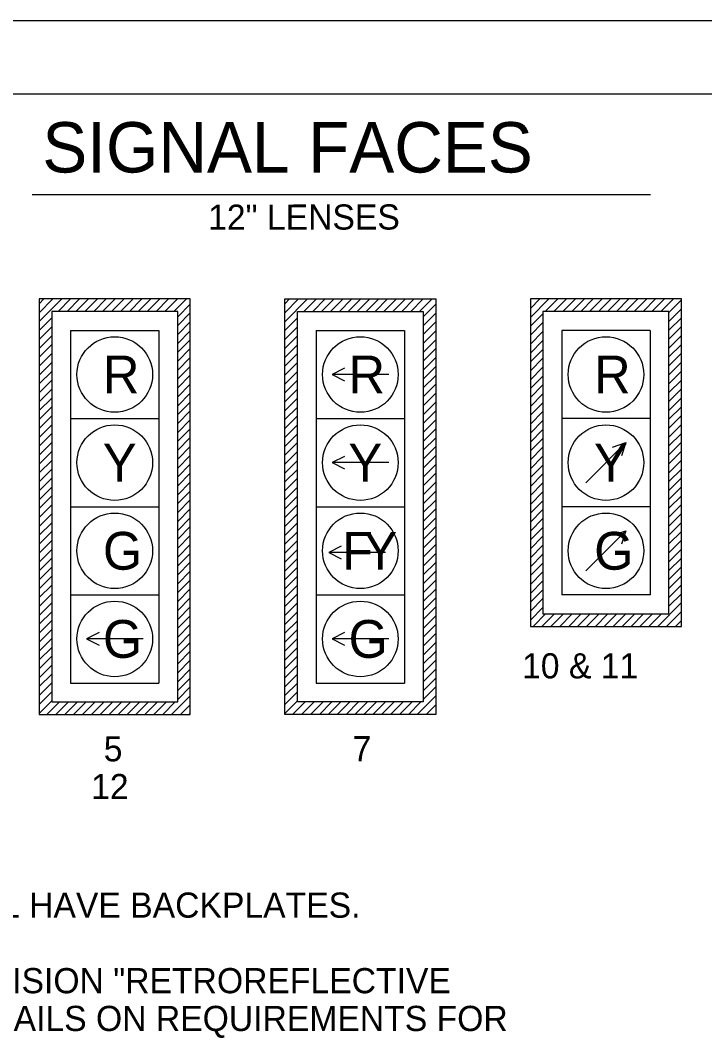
# Model space of a CAD drawing. Extents: x 1710114 to 1711114, y 557211 to 557851.
# Drawn here: x 1710384.3 to 1710492.9, y 557689.1 to 557851.1 of the extents above; entities that cross this region are included whole.
import ezdxf

# ---------------------------------------------------------------- set-up
doc = ezdxf.new("R2010")
doc.units = 0
for name, color, linetype in [('E_Existing ROW', 7, 'Continuous'), ('R_Alt Surface', 7, 'Continuous'), ('R_Alt Surface Annot', 7, 'Continuous'), ('R_Dimension', 7, 'Continuous')]:
    doc.layers.add(name, color=color, linetype=linetype)

msp = doc.modelspace()

# ---------------------------------------------------------------- linework, layer by layer
at = {"layer": 'E_Existing ROW'}
for p, q in [((1710411.23, 557806.9), (1710387.23, 557806.9)), ((1710387.23, 557806.9), (1710387.23, 557740.9)), ((1710387.23, 557803.3), (1710390.82, 557806.9)), ((1710387.23, 557804.72), (1710389.4, 557806.9)), ((1710387.23, 557806.13), (1710387.99, 557806.9)), ((1710390.23, 557804.9), (1710392.23, 557806.9)), ((1710391.65, 557804.9), (1710393.65, 557806.9)), ((1710393.06, 557804.9), (1710395.06, 557806.9)), ((1710394.48, 557804.9), (1710396.48, 557806.9)), ((1710395.89, 557804.9), (1710397.89, 557806.9)), ((1710397.3, 557804.9), (1710399.3, 557806.9)), ((1710398.72, 557804.9), (1710400.72, 557806.9)), ((1710400.13, 557804.9), (1710402.13, 557806.9)), ((1710401.55, 557804.9), (1710403.55, 557806.9)), ((1710402.96, 557804.9), (1710404.96, 557806.9)), ((1710404.38, 557804.9), (1710406.38, 557806.9)), ((1710405.79, 557804.9), (1710407.79, 557806.9)), ((1710407.2, 557804.9), (1710409.2, 557806.9)), ((1710408.62, 557804.9), (1710410.62, 557806.9)), ((1710411.23, 557740.9), (1710411.23, 557806.9)), ((1710426.23, 557740.9), (1710426.23, 557806.9)), ((1710426.23, 557806.9), (1710450.23, 557806.9)), ((1710426.23, 557803.29), (1710429.83, 557806.9)), ((1710426.23, 557804.7), (1710428.42, 557806.9)), ((1710426.23, 557806.12), (1710427, 557806.9)), ((1710429.25, 557804.9), (1710431.25, 557806.9)), ((1710430.66, 557804.9), (1710432.66, 557806.9)), ((1710432.08, 557804.9), (1710434.08, 557806.9)), ((1710433.49, 557804.9), (1710435.49, 557806.9)), ((1710434.9, 557804.9), (1710436.9, 557806.9)), ((1710436.32, 557804.9), (1710438.32, 557806.9)), ((1710437.73, 557804.9), (1710439.73, 557806.9)), ((1710439.15, 557804.9), (1710441.15, 557806.9)), ((1710440.56, 557804.9), (1710442.56, 557806.9)), ((1710441.98, 557804.9), (1710443.98, 557806.9)), ((1710443.39, 557804.9), (1710445.39, 557806.9)), ((1710444.8, 557804.9), (1710446.8, 557806.9)), ((1710446.22, 557804.9), (1710448.22, 557806.9)), ((1710447.63, 557804.9), (1710449.63, 557806.9)), ((1710450.23, 557806.9), (1710450.23, 557740.9)), ((1710489.23, 557806.9), (1710465.23, 557806.9)), ((1710465.23, 557806.9), (1710465.23, 557754.9)), ((1710465.23, 557803.97), (1710468.15, 557806.9)), ((1710465.23, 557805.39), (1710466.74, 557806.9)), ((1710465.23, 557806.8), (1710465.32, 557806.9)), ((1710467.57, 557804.9), (1710469.57, 557806.9)), ((1710468.98, 557804.9), (1710470.98, 557806.9)), ((1710470.39, 557804.9), (1710472.39, 557806.9)), ((1710471.81, 557804.9), (1710473.81, 557806.9)), ((1710473.22, 557804.9), (1710475.22, 557806.9)), ((1710474.64, 557804.9), (1710476.64, 557806.9)), ((1710476.05, 557804.9), (1710478.05, 557806.9)), ((1710477.47, 557804.9), (1710479.47, 557806.9)), ((1710478.88, 557804.9), (1710480.88, 557806.9)), ((1710480.29, 557804.9), (1710482.29, 557806.9)), ((1710481.71, 557804.9), (1710483.71, 557806.9)), ((1710483.12, 557804.9), (1710485.12, 557806.9)), ((1710484.54, 557804.9), (1710486.54, 557806.9)), ((1710485.95, 557804.9), (1710487.95, 557806.9)), ((1710487.23, 557804.76), (1710489.23, 557806.76)), ((1710489.23, 557754.9), (1710489.23, 557806.9)), ((1710409.23, 557804.09), (1710411.23, 557806.09)), ((1710448.23, 557804.08), (1710450.23, 557806.08)), ((1710487.23, 557803.34), (1710489.23, 557805.34)), ((1710387.23, 557801.89), (1710389.23, 557803.89)), ((1710409.23, 557802.68), (1710411.23, 557804.68)), ((1710409.23, 557801.26), (1710411.23, 557803.26)), ((1710426.23, 557801.88), (1710428.23, 557803.88)), ((1710448.23, 557802.66), (1710450.23, 557804.66)), ((1710448.23, 557801.25), (1710450.23, 557803.25)), ((1710465.23, 557802.56), (1710467.23, 557804.56)), ((1710465.23, 557801.14), (1710467.23, 557803.14)), ((1710487.23, 557801.93), (1710489.23, 557803.93)), ((1710387.23, 557800.48), (1710389.23, 557802.48)), ((1710392.23, 557801.9), (1710406.23, 557801.9)), ((1710392.23, 557801.9), (1710392.23, 557787.9)), ((1710406.23, 557801.9), (1710406.23, 557787.9)), ((1710409.23, 557799.85), (1710411.23, 557801.85)), ((1710426.23, 557800.46), (1710428.23, 557802.46)), ((1710431.23, 557801.9), (1710445.23, 557801.9)), ((1710431.23, 557801.9), (1710431.23, 557787.9)), ((1710445.23, 557801.9), (1710445.23, 557787.9)), ((1710448.23, 557799.83), (1710450.23, 557801.83)), ((1710465.23, 557799.73), (1710467.23, 557801.73)), ((1710484.23, 557801.9), (1710470.23, 557801.9)), ((1710470.23, 557801.9), (1710470.23, 557787.9)), ((1710484.23, 557801.9), (1710484.23, 557787.9)), ((1710487.23, 557800.52), (1710489.23, 557802.52)), ((1710387.23, 557799.06), (1710389.23, 557801.06)), ((1710409.23, 557798.43), (1710411.23, 557800.43)), ((1710426.23, 557799.05), (1710428.23, 557801.05)), ((1710448.23, 557798.42), (1710450.23, 557800.42)), ((1710465.23, 557798.31), (1710467.23, 557800.31)), ((1710487.23, 557799.1), (1710489.23, 557801.1)), ((1710387.23, 557797.65), (1710389.23, 557799.65)), ((1710409.23, 557797.02), (1710411.23, 557799.02)), ((1710426.23, 557797.63), (1710428.23, 557799.63)), ((1710448.23, 557797.01), (1710450.23, 557799.01)), ((1710465.23, 557796.9), (1710467.23, 557798.9)), ((1710487.23, 557797.69), (1710489.23, 557799.69)), ((1710487.23, 557796.27), (1710489.23, 557798.27)), ((1710387.23, 557796.23), (1710389.23, 557798.23)), ((1710387.23, 557794.82), (1710389.23, 557796.82)), ((1710409.23, 557795.61), (1710411.23, 557797.61)), ((1710426.23, 557796.22), (1710428.23, 557798.22)), ((1710426.23, 557794.8), (1710428.23, 557796.8)), ((1710448.23, 557795.59), (1710450.23, 557797.59)), ((1710465.23, 557795.49), (1710467.23, 557797.49)), ((1710487.23, 557794.86), (1710489.23, 557796.86)), ((1710387.23, 557793.4), (1710389.23, 557795.4)), ((1710409.23, 557794.19), (1710411.23, 557796.19)), ((1710426.23, 557793.39), (1710428.23, 557795.39)), ((1710448.23, 557794.18), (1710450.23, 557796.18)), ((1710465.23, 557794.07), (1710467.23, 557796.07)), ((1710487.23, 557793.44), (1710489.23, 557795.44)), ((1710387.23, 557791.99), (1710389.23, 557793.99)), ((1710409.23, 557792.78), (1710411.23, 557794.78)), ((1710426.23, 557791.98), (1710428.23, 557793.98)), ((1710442.73, 557794.9), (1710433.73, 557794.9)), ((1710448.23, 557792.76), (1710450.23, 557794.76)), ((1710465.23, 557792.66), (1710467.23, 557794.66)), ((1710487.23, 557792.03), (1710489.23, 557794.03)), ((1710387.23, 557790.58), (1710389.23, 557792.58)), ((1710409.23, 557791.36), (1710411.23, 557793.36)), ((1710409.23, 557789.95), (1710411.23, 557791.95)), ((1710426.23, 557790.56), (1710428.23, 557792.56)), ((1710448.23, 557791.35), (1710450.23, 557793.35)), ((1710448.23, 557789.93), (1710450.23, 557791.93)), ((1710465.23, 557791.24), (1710467.23, 557793.24)), ((1710465.23, 557789.83), (1710467.23, 557791.83)), ((1710487.23, 557790.62), (1710489.23, 557792.62)), ((1710387.23, 557789.16), (1710389.23, 557791.16)), ((1710409.23, 557788.53), (1710411.23, 557790.53)), ((1710426.23, 557789.15), (1710428.23, 557791.15)), ((1710448.23, 557788.52), (1710450.23, 557790.52)), ((1710465.23, 557788.42), (1710467.23, 557790.42)), ((1710487.23, 557789.2), (1710489.23, 557791.2)), ((1710387.23, 557787.75), (1710389.23, 557789.75)), ((1710409.23, 557787.12), (1710411.23, 557789.12)), ((1710426.23, 557787.73), (1710428.23, 557789.73)), ((1710448.23, 557787.11), (1710450.23, 557789.11)), ((1710465.23, 557787), (1710467.23, 557789)), ((1710487.23, 557787.79), (1710489.23, 557789.79)), ((1710387.23, 557786.33), (1710389.23, 557788.33)), ((1710387.23, 557784.92), (1710389.23, 557786.92)), ((1710392.23, 557787.9), (1710406.23, 557787.9)), ((1710392.23, 557787.9), (1710392.23, 557773.9)), ((1710406.23, 557787.9), (1710406.23, 557773.9)), ((1710409.23, 557785.71), (1710411.23, 557787.71)), ((1710426.23, 557786.32), (1710428.23, 557788.32)), ((1710431.23, 557787.9), (1710445.23, 557787.9)), ((1710431.23, 557787.9), (1710431.23, 557773.9)), ((1710445.23, 557787.9), (1710445.23, 557773.9)), ((1710448.23, 557785.69), (1710450.23, 557787.69)), ((1710465.23, 557785.59), (1710467.23, 557787.59)), ((1710484.23, 557787.9), (1710470.23, 557787.9)), ((1710470.23, 557787.9), (1710470.23, 557773.9)), ((1710484.23, 557787.9), (1710484.23, 557773.9)), ((1710487.23, 557786.37), (1710489.23, 557788.37)), ((1710487.23, 557784.96), (1710489.23, 557786.96)), ((1710387.23, 557783.51), (1710389.23, 557785.51)), ((1710409.23, 557784.29), (1710411.23, 557786.29)), ((1710426.23, 557784.91), (1710428.23, 557786.91)), ((1710426.23, 557783.49), (1710428.23, 557785.49)), ((1710448.23, 557784.28), (1710450.23, 557786.28)), ((1710465.23, 557784.17), (1710467.23, 557786.17)), ((1710487.23, 557783.55), (1710489.23, 557785.55)), ((1710387.23, 557782.09), (1710389.23, 557784.09)), ((1710409.23, 557782.88), (1710411.23, 557784.88)), ((1710426.23, 557782.08), (1710428.23, 557784.08)), ((1710448.23, 557782.86), (1710450.23, 557784.86)), ((1710465.23, 557782.76), (1710467.23, 557784.76)), ((1710474.04, 557777.72), (1710480.41, 557784.08)), ((1710487.23, 557782.13), (1710489.23, 557784.13)), ((1710387.23, 557780.68), (1710389.23, 557782.68)), ((1710409.23, 557781.46), (1710411.23, 557783.46)), ((1710426.23, 557780.66), (1710428.23, 557782.66)), ((1710448.23, 557781.45), (1710450.23, 557783.45)), ((1710465.23, 557781.34), (1710467.23, 557783.34)), ((1710487.23, 557780.72), (1710489.23, 557782.72)), ((1710387.23, 557779.26), (1710389.23, 557781.26)), ((1710409.23, 557780.05), (1710411.23, 557782.05)), ((1710409.23, 557778.64), (1710411.23, 557780.64)), ((1710426.23, 557779.25), (1710428.23, 557781.25)), ((1710442.73, 557780.9), (1710433.73, 557780.9)), ((1710448.23, 557780.04), (1710450.23, 557782.04)), ((1710448.23, 557778.62), (1710450.23, 557780.62)), ((1710465.23, 557779.93), (1710467.23, 557781.93)), ((1710465.23, 557778.52), (1710467.23, 557780.52)), ((1710487.23, 557779.3), (1710489.23, 557781.3)), ((1710387.23, 557777.85), (1710389.23, 557779.85)), ((1710409.23, 557777.22), (1710411.23, 557779.22)), ((1710426.23, 557777.83), (1710428.23, 557779.83)), ((1710448.23, 557777.21), (1710450.23, 557779.21)), ((1710465.23, 557777.1), (1710467.23, 557779.1)), ((1710487.23, 557777.89), (1710489.23, 557779.89)), ((1710387.23, 557776.43), (1710389.23, 557778.43)), ((1710409.23, 557775.81), (1710411.23, 557777.81)), ((1710426.23, 557776.42), (1710428.23, 557778.42)), ((1710448.23, 557775.79), (1710450.23, 557777.79)), ((1710465.23, 557775.69), (1710467.23, 557777.69)), ((1710487.23, 557776.47), (1710489.23, 557778.47)), ((1710387.23, 557775.02), (1710389.23, 557777.02)), ((1710387.23, 557773.61), (1710389.23, 557775.61)), ((1710409.23, 557774.39), (1710411.23, 557776.39)), ((1710426.23, 557775.01), (1710428.23, 557777.01)), ((1710426.23, 557773.59), (1710428.23, 557775.59)), ((1710448.23, 557774.38), (1710450.23, 557776.38)), ((1710465.23, 557774.27), (1710467.23, 557776.27)), ((1710487.23, 557775.06), (1710489.23, 557777.06)), ((1710487.23, 557773.65), (1710489.23, 557775.65)), ((1710387.23, 557772.19), (1710389.23, 557774.19)), ((1710409.23, 557772.98), (1710411.23, 557774.98)), ((1710426.23, 557772.18), (1710428.23, 557774.18)), ((1710448.23, 557772.96), (1710450.23, 557774.96)), ((1710465.23, 557772.86), (1710467.23, 557774.86)), ((1710487.23, 557772.23), (1710489.23, 557774.23)), ((1710387.23, 557770.78), (1710389.23, 557772.78)), ((1710392.23, 557773.9), (1710406.23, 557773.9)), ((1710392.23, 557773.9), (1710392.23, 557759.9)), ((1710406.23, 557773.9), (1710406.23, 557759.9)), ((1710409.23, 557771.56), (1710411.23, 557773.56)), ((1710426.23, 557770.76), (1710428.23, 557772.76)), ((1710431.23, 557773.9), (1710445.23, 557773.9)), ((1710431.23, 557773.9), (1710431.23, 557759.9)), ((1710445.23, 557773.9), (1710445.23, 557759.9)), ((1710448.23, 557771.55), (1710450.23, 557773.55)), ((1710465.23, 557771.44), (1710467.23, 557773.44)), ((1710484.23, 557773.9), (1710470.23, 557773.9)), ((1710470.23, 557773.9), (1710470.23, 557759.9)), ((1710484.23, 557773.9), (1710484.23, 557759.9)), ((1710487.23, 557770.82), (1710489.23, 557772.82)), ((1710387.23, 557769.36), (1710389.23, 557771.36)), ((1710409.23, 557770.15), (1710411.23, 557772.15)), ((1710409.23, 557768.74), (1710411.23, 557770.74)), ((1710426.23, 557769.35), (1710428.23, 557771.35)), ((1710448.23, 557770.14), (1710450.23, 557772.14)), ((1710448.23, 557768.72), (1710450.23, 557770.72)), ((1710465.23, 557770.03), (1710467.23, 557772.03)), ((1710487.23, 557769.4), (1710489.23, 557771.4)), ((1710387.23, 557767.95), (1710389.23, 557769.95)), ((1710409.23, 557767.32), (1710411.23, 557769.32)), ((1710426.23, 557767.93), (1710428.23, 557769.93)), ((1710448.23, 557767.31), (1710450.23, 557769.31)), ((1710465.23, 557768.62), (1710467.23, 557770.62)), ((1710465.23, 557767.2), (1710467.23, 557769.2)), ((1710474.04, 557763.72), (1710480.41, 557770.08)), ((1710487.23, 557767.99), (1710489.23, 557769.99)), ((1710387.23, 557766.53), (1710389.23, 557768.53)), ((1710409.23, 557765.91), (1710411.23, 557767.91)), ((1710426.23, 557766.52), (1710428.23, 557768.52)), ((1710448.23, 557765.89), (1710450.23, 557767.89)), ((1710465.23, 557765.79), (1710467.23, 557767.79)), ((1710487.23, 557766.57), (1710489.23, 557768.57)), ((1710387.23, 557765.12), (1710389.23, 557767.12)), ((1710409.23, 557764.49), (1710411.23, 557766.49)), ((1710426.23, 557765.11), (1710428.23, 557767.11)), ((1710442.2, 557766.62), (1710433.2, 557766.62)), ((1710448.23, 557764.48), (1710450.23, 557766.48)), ((1710465.23, 557764.37), (1710467.23, 557766.37)), ((1710487.23, 557765.16), (1710489.23, 557767.16)), ((1710387.23, 557763.71), (1710389.23, 557765.71)), ((1710387.23, 557762.29), (1710389.23, 557764.29)), ((1710409.23, 557763.08), (1710411.23, 557765.08)), ((1710426.23, 557763.69), (1710428.23, 557765.69)), ((1710426.23, 557762.28), (1710428.23, 557764.28)), ((1710448.23, 557763.06), (1710450.23, 557765.06)), ((1710465.23, 557762.96), (1710467.23, 557764.96)), ((1710487.23, 557763.75), (1710489.23, 557765.75)), ((1710487.23, 557762.33), (1710489.23, 557764.33)), ((1710387.23, 557760.88), (1710389.23, 557762.88)), ((1710409.23, 557761.66), (1710411.23, 557763.66)), ((1710426.23, 557760.86), (1710428.23, 557762.86)), ((1710448.23, 557761.65), (1710450.23, 557763.65)), ((1710465.23, 557761.55), (1710467.23, 557763.55)), ((1710487.23, 557760.92), (1710489.23, 557762.92)), ((1710387.23, 557759.46), (1710389.23, 557761.46)), ((1710409.23, 557760.25), (1710411.23, 557762.25)), ((1710426.23, 557759.45), (1710428.23, 557761.45)), ((1710448.23, 557760.24), (1710450.23, 557762.24)), ((1710465.23, 557760.13), (1710467.23, 557762.13)), ((1710487.23, 557759.5), (1710489.23, 557761.5)), ((1710387.23, 557758.05), (1710389.23, 557760.05)), ((1710392.23, 557759.9), (1710406.23, 557759.9)), ((1710392.23, 557759.9), (1710392.23, 557745.9)), ((1710406.23, 557759.9), (1710406.23, 557745.9)), ((1710409.23, 557758.84), (1710411.23, 557760.84)), ((1710409.23, 557757.42), (1710411.23, 557759.42)), ((1710426.23, 557758.04), (1710428.23, 557760.04)), ((1710431.23, 557759.9), (1710445.23, 557759.9)), ((1710431.23, 557759.9), (1710431.23, 557745.9)), ((1710445.23, 557759.9), (1710445.23, 557745.9)), ((1710448.23, 557758.82), (1710450.23, 557760.82)), ((1710448.23, 557757.41), (1710450.23, 557759.41)), ((1710465.23, 557758.72), (1710467.23, 557760.72)), ((1710484.23, 557759.9), (1710470.23, 557759.9)), ((1710487.23, 557758.09), (1710489.23, 557760.09)), ((1710387.23, 557756.64), (1710389.23, 557758.64)), ((1710409.23, 557756.01), (1710411.23, 557758.01)), ((1710426.23, 557756.62), (1710428.23, 557758.62)), ((1710448.23, 557755.99), (1710450.23, 557757.99)), ((1710465.23, 557757.3), (1710467.23, 557759.3)), ((1710465.23, 557755.89), (1710467.23, 557757.89)), ((1710485.45, 557754.9), (1710489.23, 557758.68)), ((1710387.23, 557755.22), (1710389.23, 557757.22)), ((1710409.23, 557754.59), (1710411.23, 557756.59)), ((1710426.23, 557755.21), (1710428.23, 557757.21)), ((1710448.23, 557754.58), (1710450.23, 557756.58)), ((1710465.65, 557754.9), (1710467.65, 557756.9)), ((1710467.06, 557754.9), (1710469.06, 557756.9)), ((1710468.48, 557754.9), (1710470.48, 557756.9)), ((1710469.89, 557754.9), (1710471.89, 557756.9)), ((1710471.31, 557754.9), (1710473.31, 557756.9)), ((1710472.72, 557754.9), (1710474.72, 557756.9)), ((1710474.13, 557754.9), (1710476.13, 557756.9)), ((1710475.55, 557754.9), (1710477.55, 557756.9)), ((1710476.96, 557754.9), (1710478.96, 557756.9)), ((1710478.38, 557754.9), (1710480.38, 557756.9)), ((1710479.79, 557754.9), (1710481.79, 557756.9)), ((1710481.21, 557754.9), (1710483.21, 557756.9)), ((1710482.62, 557754.9), (1710484.62, 557756.9)), ((1710484.03, 557754.9), (1710486.03, 557756.9)), ((1710486.86, 557754.9), (1710489.23, 557757.26)), ((1710387.23, 557753.81), (1710389.23, 557755.81)), ((1710409.23, 557753.18), (1710411.23, 557755.18)), ((1710426.23, 557753.79), (1710428.23, 557755.79)), ((1710448.23, 557753.17), (1710450.23, 557755.17)), ((1710465.23, 557754.9), (1710489.23, 557754.9)), ((1710488.28, 557754.9), (1710489.23, 557755.85)), ((1710387.23, 557752.39), (1710389.23, 557754.39)), ((1710387.23, 557750.98), (1710389.23, 557752.98)), ((1710403.73, 557752.9), (1710394.73, 557752.9)), ((1710409.23, 557751.77), (1710411.23, 557753.77)), ((1710426.23, 557752.38), (1710428.23, 557754.38)), ((1710426.23, 557750.96), (1710428.23, 557752.96)), ((1710442.73, 557752.9), (1710433.73, 557752.9)), ((1710448.23, 557751.75), (1710450.23, 557753.75)), ((1710387.23, 557749.56), (1710389.23, 557751.56)), ((1710409.23, 557750.35), (1710411.23, 557752.35)), ((1710426.23, 557749.55), (1710428.23, 557751.55)), ((1710448.23, 557750.34), (1710450.23, 557752.34)), ((1710387.23, 557748.15), (1710389.23, 557750.15)), ((1710409.23, 557748.94), (1710411.23, 557750.94)), ((1710426.23, 557748.14), (1710428.23, 557750.14)), ((1710448.23, 557748.92), (1710450.23, 557750.92)), ((1710387.23, 557746.74), (1710389.23, 557748.74)), ((1710409.23, 557747.52), (1710411.23, 557749.52)), ((1710409.23, 557746.11), (1710411.23, 557748.11)), ((1710426.23, 557746.72), (1710428.23, 557748.72)), ((1710448.23, 557747.51), (1710450.23, 557749.51)), ((1710448.23, 557746.09), (1710450.23, 557748.09)), ((1710387.23, 557745.32), (1710389.23, 557747.32)), ((1710409.23, 557744.69), (1710411.23, 557746.69)), ((1710426.23, 557745.31), (1710428.23, 557747.31)), ((1710448.23, 557744.68), (1710450.23, 557746.68)), ((1710387.23, 557743.91), (1710389.23, 557745.91)), ((1710392.23, 557745.9), (1710406.23, 557745.9)), ((1710409.23, 557743.28), (1710411.23, 557745.28)), ((1710426.23, 557743.89), (1710428.23, 557745.89)), ((1710431.23, 557745.9), (1710445.23, 557745.9)), ((1710448.23, 557743.27), (1710450.23, 557745.27)), ((1710387.23, 557742.49), (1710389.23, 557744.49)), ((1710408.26, 557740.9), (1710411.23, 557743.87)), ((1710426.23, 557742.48), (1710428.23, 557744.48)), ((1710447.27, 557740.9), (1710450.23, 557743.85)), ((1710387.23, 557741.08), (1710389.23, 557743.08)), ((1710388.46, 557740.9), (1710390.46, 557742.9)), ((1710389.87, 557740.9), (1710391.87, 557742.9)), ((1710391.29, 557740.9), (1710393.29, 557742.9)), ((1710392.7, 557740.9), (1710394.7, 557742.9)), ((1710394.12, 557740.9), (1710396.12, 557742.9)), ((1710395.53, 557740.9), (1710397.53, 557742.9)), ((1710396.94, 557740.9), (1710398.94, 557742.9)), ((1710398.36, 557740.9), (1710400.36, 557742.9)), ((1710399.77, 557740.9), (1710401.77, 557742.9)), ((1710401.19, 557740.9), (1710403.19, 557742.9)), ((1710402.6, 557740.9), (1710404.6, 557742.9)), ((1710404.01, 557740.9), (1710406.01, 557742.9)), ((1710405.43, 557740.9), (1710407.43, 557742.9)), ((1710406.84, 557740.9), (1710408.84, 557742.9)), ((1710409.67, 557740.9), (1710411.23, 557742.45)), ((1710426.23, 557741.06), (1710428.23, 557743.06)), ((1710427.47, 557740.9), (1710429.47, 557742.9)), ((1710428.89, 557740.9), (1710430.89, 557742.9)), ((1710430.3, 557740.9), (1710432.3, 557742.9)), ((1710431.72, 557740.9), (1710433.72, 557742.9)), ((1710433.13, 557740.9), (1710435.13, 557742.9)), ((1710434.54, 557740.9), (1710436.54, 557742.9)), ((1710435.96, 557740.9), (1710437.96, 557742.9)), ((1710437.37, 557740.9), (1710439.37, 557742.9)), ((1710438.79, 557740.9), (1710440.79, 557742.9)), ((1710440.2, 557740.9), (1710442.2, 557742.9)), ((1710441.61, 557740.9), (1710443.61, 557742.9)), ((1710443.03, 557740.9), (1710445.03, 557742.9)), ((1710444.44, 557740.9), (1710446.44, 557742.9)), ((1710445.86, 557740.9), (1710447.86, 557742.9)), ((1710448.69, 557740.9), (1710450.23, 557742.44)), ((1710387.23, 557740.9), (1710411.23, 557740.9)), ((1710411.09, 557740.9), (1710411.23, 557741.04)), ((1710450.23, 557740.9), (1710426.23, 557740.9)), ((1710450.1, 557740.9), (1710450.23, 557741.02))]:
    msp.add_line(p, q, dxfattribs=at)
for points in [[(1710409.23, 557804.9), (1710389.23, 557804.9), (1710389.23, 557742.9), (1710409.23, 557742.9)], [(1710428.23, 557742.9), (1710428.23, 557804.9), (1710448.23, 557804.9), (1710448.23, 557742.9)], [(1710487.23, 557804.9), (1710467.23, 557804.9), (1710467.23, 557756.9), (1710487.23, 557756.9)]]:
    msp.add_lwpolyline(points, close=True, dxfattribs=at)
for points in [[(1710435.73, 557795.9), (1710433.73, 557794.9), (1710435.73, 557793.9)], [(1710478.29, 557783.37), (1710480.41, 557784.08), (1710479.7, 557781.96)], [(1710435.73, 557781.9), (1710433.73, 557780.9), (1710435.73, 557779.9)], [(1710478.29, 557769.37), (1710480.41, 557770.08), (1710479.7, 557767.96)], [(1710435.2, 557767.62), (1710433.2, 557766.62), (1710435.2, 557765.62)], [(1710396.73, 557753.9), (1710394.73, 557752.9), (1710396.73, 557751.9)], [(1710435.73, 557753.9), (1710433.73, 557752.9), (1710435.73, 557751.9)]]:
    msp.add_lwpolyline(points, dxfattribs=at)
for centre in [(1710399.23, 557794.9), (1710438.23, 557794.9), (1710477.23, 557794.9), (1710399.23, 557780.9), (1710438.23, 557780.9), (1710477.23, 557780.9), (1710399.23, 557766.9), (1710438.23, 557766.9), (1710477.23, 557766.9), (1710399.23, 557752.9), (1710438.23, 557752.9)]:
    msp.add_circle(centre, 6, dxfattribs=at)
at = {"layer": 'R_Alt Surface'}
msp.add_line((1710151.54, 557839.47), (1711100.08, 557839.47), dxfattribs=at)
at = {"layer": 'R_Alt Surface Annot'}
msp.add_line((1710114.34, 557851.15), (1711114.34, 557851.15), dxfattribs=at)
msp.add_lwpolyline([(1710114.32, 557851.15), (1711114.34, 557851.15), (1711114.34, 557211.14), (1710114.32, 557211.14)], close=True, dxfattribs=at)
at = {"layer": 'R_Dimension'}
msp.add_line((1710386.13, 557823.52), (1710484.32, 557823.52), dxfattribs=at)

# ---------------------------------------------------------------- texts
at = {"layer": 'E_Existing ROW'}
msp.add_text('12" LENSES', height=4, rotation=0.072, dxfattribs=at).set_placement((1710414.06, 557817.89))
for s, p in [('R', (1710397.36, 557791.9)), ('R', (1710436.36, 557791.9)), ('R', (1710475.36, 557791.9)), ('Y', (1710397.34, 557777.9)), ('Y', (1710436.34, 557777.9)), ('Y', (1710475.34, 557777.9)), ('G', (1710397.36, 557763.9)), ('F', (1710435.32, 557763.9)), ('Y', (1710438.75, 557763.9)), ('G', (1710475.36, 557763.9)), ('G', (1710397.36, 557749.9)), ('G', (1710436.36, 557749.9))]:
    msp.add_text(s, height=6, dxfattribs=at).set_placement(p)
at = {"layer": 'R_Dimension'}
for s, height, p in [('SIGNAL FACES', 8, (1710387.73, 557826.99)), ('10 & 11', 4, (1710463.91, 557746.63)), ('5', 4, (1710397.48, 557733.45)), ('7', 4, (1710437, 557733.46)), ('12', 4, (1710395.48, 557727.45)), ('1. ALL SIGNAL HEADS SHALL HAVE BACKPLATES.', 4, (1710309.23, 557708.62)), ('2. REFER TO SPECIAL PROVISION "RETROREFLECTIVE', 4, (1710309.23, 557696.62)), ('BACKPLATES" FOR DETAILS ON REQUIREMENTS FOR ', 4, (1710321.23, 557690.62))]:
    msp.add_text(s, height=height, dxfattribs=at).set_placement(p)

doc.saveas('drawing.dxf')
